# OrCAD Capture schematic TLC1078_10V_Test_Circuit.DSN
size A; title: TLC1078, TLC1078Y, TLC1079, TLC1079Y LinCMOS µPOWER; rev: 1.1; note: Datasheet: SLOS179A EVM: N/A
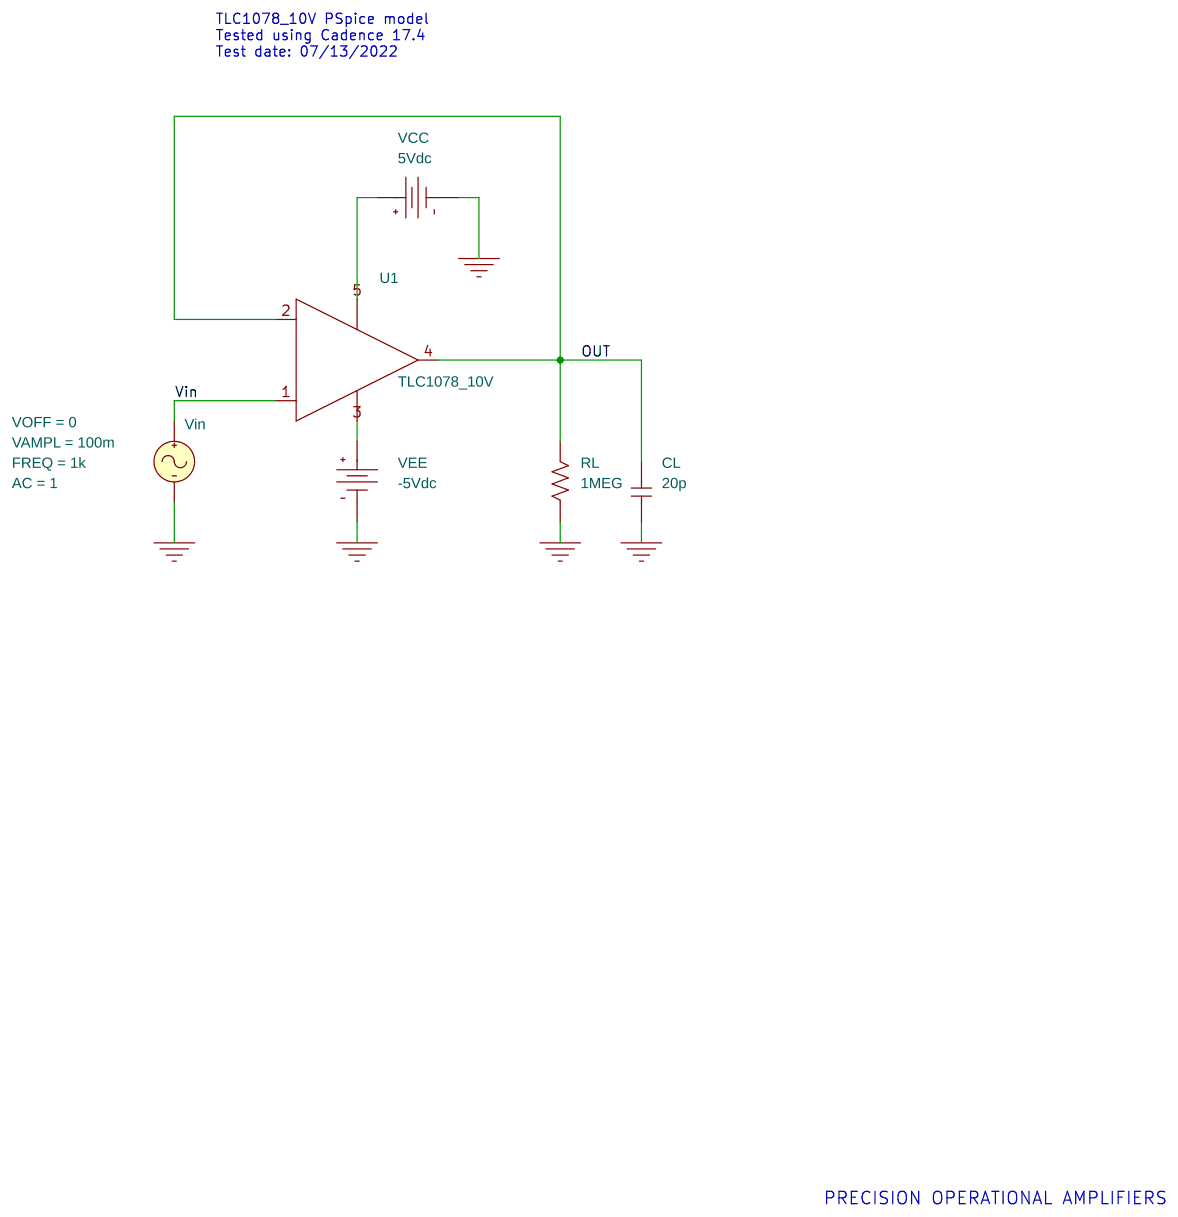
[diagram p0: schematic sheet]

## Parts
CL  20p  [RAD/CK05]
RL  1MEG  [AX/RC05]
U1  TLC1078_10V
VCC  VDC
VEE  VDC
Vin  VSIN

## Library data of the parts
CL = C
RL = R
U1 = TLC1078_10V
VCC = VDC: DC: 5Vdc
VEE = VDC: DC: -5Vdc
Vin = VSIN: AC: 1; FREQ: 1k; VAMPL: 100m; VOFF: 0

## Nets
Vin: U1.1(+) Vin.1(+)
0: CL.1 RL.1 VCC.1(-) VEE.1(-) Vin.2(-)
OUT: CL.2 RL.2 U1.2(-) U1.4(OUT)
N22995: U1.5(V+) VCC.0(+)
N23017: U1.3(V-) VEE.0(+)

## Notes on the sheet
- TLC1078_10V PSpice model
  Tested using Cadence 17.4
  Test date: 07/13/2022
- PRECISION OPERATIONAL AMPLIFIERS
